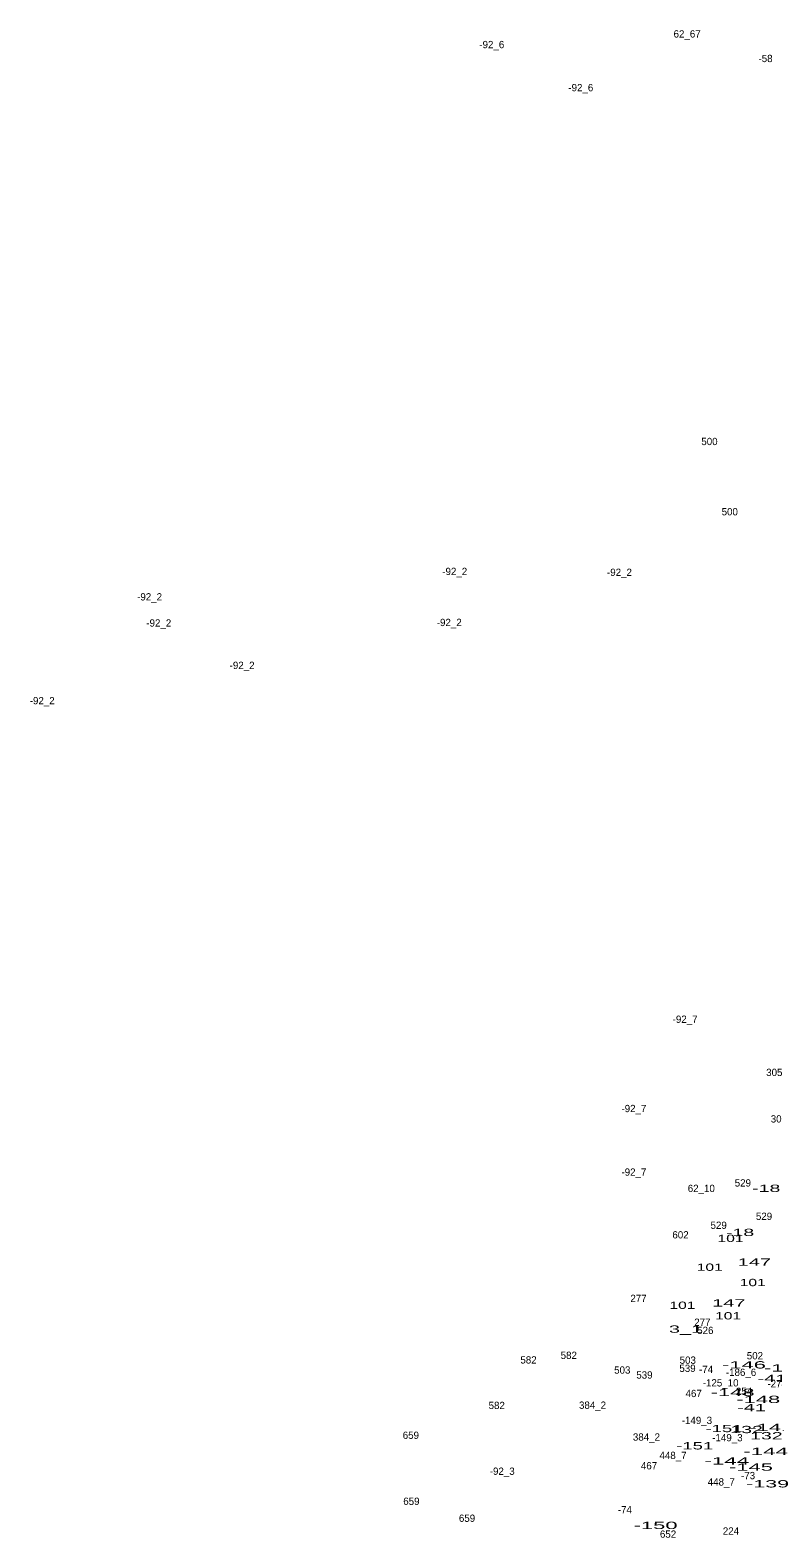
# Model space of a CAD drawing. Extents: x -661742 to -657295, y -1002932 to -996888.
# Drawn here: x -660423 to -660015, y -1000678 to -999850 of the extents above; entities that cross this region are included whole.
import ezdxf
from ezdxf.enums import TextEntityAlignment as Align

# ---------------------------------------------------------------- set-up
doc = ezdxf.new("R2010")
doc.units = 0
doc.header["$LTSCALE"] = 1.6
doc.layers.add('24', color=7, linetype='Continuous')

msp = doc.modelspace()

# ---------------------------------------------------------------- texts
at = {"layer": '24'}
for s, p in [('-92_6', (-660169.263, -999859.73)), ('62_67', (-660062.041, -999853.88)), ('-58', (-660018.995, -999867.38)), ('-92_6', (-660120.403, -999883.39)), ('500', (-660049.775, -1000077.79)), ('500', (-660038.635, -1000116.38)), ('-92_2', (-660189.608, -1000149.19)), ('-92_2', (-660099.178, -1000149.67)), ('-92_2', (-660357.128, -1000163.15)), ('-92_2', (-660352.078, -1000177.51)), ('-92_2', (-660192.628, -1000177.21)), ('-92_2', (-660306.328, -1000200.78)), ('-92_2', (-660416.068, -1000220.18)), ('-92_7', (-660063.134, -1000395.19)), ('305', (-660014.181, -1000424.41)), ('-92_7', (-660091.254, -1000444.26)), ('305', (-660011.671, -1000449.95)), ('-92_7', (-660091.254, -1000479.17)), ('62_10', (-660054.248, -1000488.14)), ('529', (-660031.453, -1000485.12)), ('529', (-660019.823, -1000503.47)), ('602', (-660065.667, -1000513.64)), ('529', (-660044.733, -1000508.39)), ('277', (-660088.729, -1000548.56)), ('277', (-660053.679, -1000561.67)), ('526', (-660052.043, -1000566.15)), ('582', (-660127.007, -1000579.84)), ('502', (-660024.821, -1000580.06)), ('582', (-660149.107, -1000582.36)), ('503', (-660097.641, -1000587.93)), ('539', (-660061.833, -1000586.96)), ('503', (-660061.681, -1000582.5)), ('-74', (-660051.645, -1000587.56)), ('-186_6', (-660032.447, -1000589.17)), ('539', (-660085.483, -1000590.65)), ('-125_10', (-660043.643, -1000594.96)), ('-274', (-660012.615, -1000595.45)), ('467', (-660058.443, -1000600.81)), ('254', (-660030.801, -1000599.61)), ('582', (-660166.557, -1000607.38)), ('384_2', (-660113.96, -1000607.23)), ('-149_3', (-660056.656, -1000615.59)), ('659', (-660213.688, -1000623.76)), ('384_2', (-660084.37, -1000624.74)), ('-149_3', (-660039.916, -1000625.08)), ('448_7', (-660069.779, -1000634.85)), ('-92_3', (-660163.538, -1000643.51)), ('467', (-660082.963, -1000640.51)), ('-73', (-660028.581, -1000645.91)), ('448_7', (-660043.299, -1000649.39)), ('659', (-660213.398, -1000660.03)), ('659', (-660182.858, -1000669.33)), ('-74', (-660096.235, -1000664.67)), ('652', (-660072.513, -1000678.07)), ('224', (-660037.971, -1000676.37))]:
    msp.add_text(s, height=4, dxfattribs=at).set_placement(p, align=Align.CENTER)
for s, width, p in [('-18', 2, (-660018.601, -1000488.09)), ('-18', 2, (-660032.951, -1000512.33)), ('101', 1.6, (-660038.21, -1000515.57)), ('101', 1.6, (-660049.62, -1000531.43)), ('147', 2.05, (-660025.138, -1000528.63)), ('101', 1.6, (-660026.02, -1000539.85)), ('101', 1.6, (-660064.61, -1000552.33)), ('147', 2.05, (-660039.158, -1000551.08)), ('101', 1.6, (-660039.56, -1000558.13)), ('3_1', 2.05, (-660062.889, -1000565.44)), ('-146', 2.25, (-660030.821, -1000585.08)), ('-148', 2.25, (-660007.786, -1000586.8)), ('-41', 2.05, (-660015.446, -1000592.55)), ('-148', 2.25, (-660037.056, -1000600.18)), ('-148', 2.25, (-660022.996, -1000604.06)), ('-41', 2.05, (-660026.686, -1000608.55)), ('-151', 1.9, (-660041.787, -1000620.05)), ('132', 2, (-660029.407, -1000620.6)), ('-145', 2.25, (-660015.826, -1000619.48)), ('-151', 1.9, (-660057.877, -1000629.56)), ('132', 2, (-660018.537, -1000624.04)), ('-144', 2.3, (-660040.262, -1000637.85)), ('-144', 2.3, (-660018.932, -1000632.61)), ('-145', 2.25, (-660026.976, -1000641.24)), ('-139', 2.2, (-660017.855, -1000650.43)), ('-150', 2.25, (-660079.347, -1000673.28))]:
    msp.add_text(s, height=4, dxfattribs=dict(at, width=width)).set_placement(p, align=Align.CENTER)

doc.saveas('drawing.dxf')
